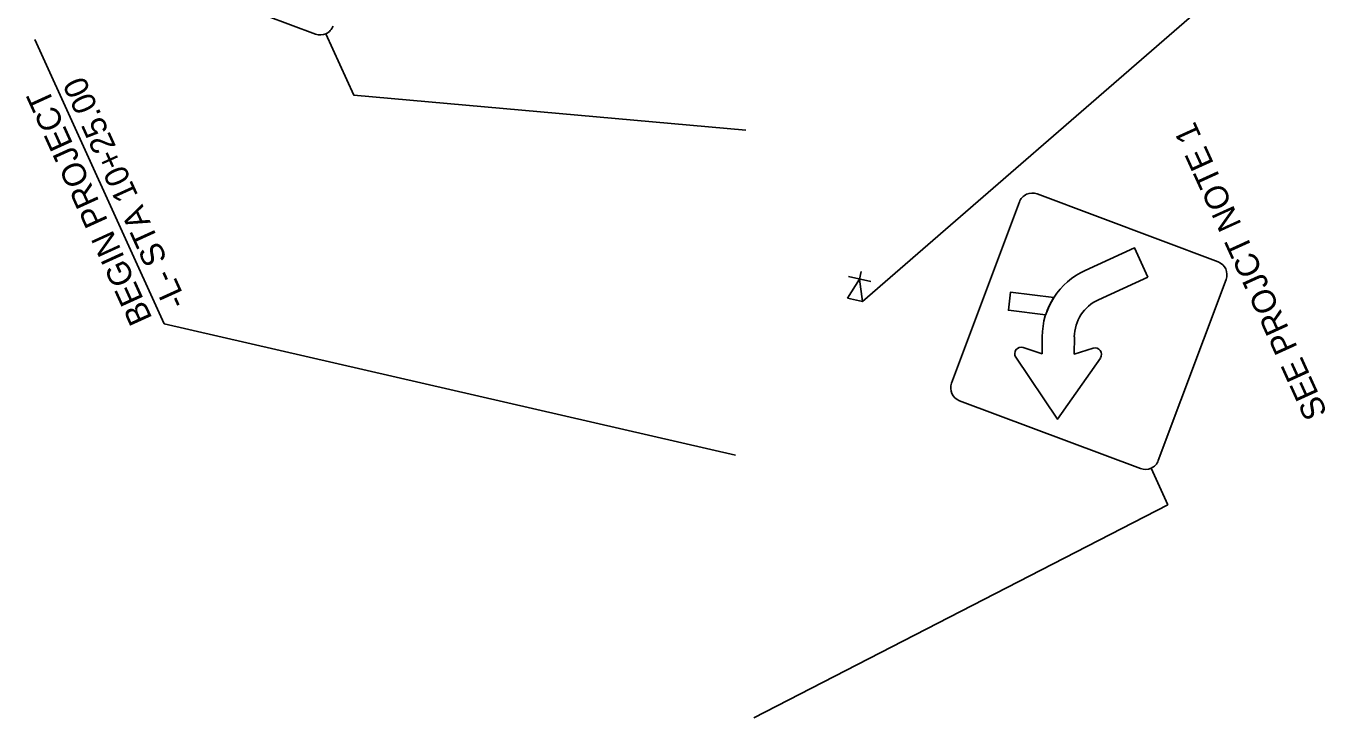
# Model space of a CAD drawing. Extents: x 2093420 to 2100301, y 676254 to 688367.
# Drawn here: x 2096431.2 to 2096816.5, y 683545.9 to 683750.8 of the extents above; entities that cross this region are included whole.
import ezdxf

# ---------------------------------------------------------------- set-up
doc = ezdxf.new("R2010")
doc.units = 0
for name, color, linetype in [('Default', 7, 'Continuous'), ('Exist Sign E Curve Left CELL', 7, 'Continuous'), ('Prop Horizontal Alignment Station Label', 7, 'Continuous')]:
    doc.layers.add(name, color=color, linetype=linetype)

msp = doc.modelspace()

# ---------------------------------------------------------------- linework, layer by layer
at = {"layer": 'Default'}
for p, q in [((2096678.06, 683675.89), (2096678.59, 683678.14)), ((2096674.52, 683670.25), (2096678.06, 683675.89)), ((2096681.4, 683675.11), (2096674.77, 683676.66)), ((2096678.06, 683675.89), (2096678.98, 683669.21)), ((2096678.98, 683669.21), (2096674.52, 683670.25)), ((2096764.44, 683619.87), (2096769.35, 683609.07))]:
    msp.add_line(p, q, dxfattribs=at)
for points in [[(2096775.78, 683769.09), (2096780.98, 683757.66), (2096678.98, 683669.21)], [(2096520.03, 683748.5), (2096528.29, 683730.35), (2096644.42, 683719.91)], [(2096769.35, 683609.07), (2096769.35, 683609.07), (2096646.79, 683545.94)]]:
    msp.add_lwpolyline(points, dxfattribs=at)
at = {"layer": 'Exist Sign E Curve Left CELL'}
for p, q in [((2096463.32, 683768.48), (2096516.91, 683748.4)), ((2096784.26, 683680.99), (2096730.67, 683701.07)), ((2096725.42, 683698.69), (2096705.34, 683645.1)), ((2096763.49, 683676.41), (2096748.87, 683669.77)), ((2096763.49, 683676.41), (2096748.87, 683669.77)), ((2096763.49, 683676.41), (2096748.87, 683669.77)), ((2096766.57, 683622.15), (2096786.65, 683675.74)), ((2096707.73, 683639.85), (2096761.32, 683619.76))]:
    msp.add_line(p, q, dxfattribs=at)
for points in [[(2096744.93, 683678.44), (2096759.54, 683685.08), (2096763.49, 683676.41)], [(2096744.93, 683678.44), (2096759.54, 683685.08), (2096763.49, 683676.41)], [(2096744.93, 683678.44), (2096759.54, 683685.08), (2096763.49, 683676.41)], [(2096735.65, 683670.43), (2096722.83, 683672.02), (2096722.16, 683666.62), (2096733.2, 683665.24)], [(2096726.53, 683655.59), (2096732.13, 683653.76), (2096732.18, 683658.81)], [(2096726.53, 683655.59), (2096732.13, 683653.76), (2096732.18, 683658.81)], [(2096726.53, 683655.59), (2096732.13, 683653.76), (2096732.18, 683658.81)], [(2096741.7, 683658.73), (2096741.66, 683653.68), (2096747.28, 683655.41)], [(2096741.7, 683658.73), (2096741.66, 683653.68), (2096747.28, 683655.41)], [(2096741.7, 683658.73), (2096741.66, 683653.68), (2096747.28, 683655.41)], [(2096749.41, 683652.5), (2096736.73, 683634.35), (2096724.36, 683652.71)], [(2096749.41, 683652.5), (2096736.73, 683634.35), (2096724.36, 683652.71)], [(2096749.41, 683652.5), (2096736.73, 683634.35), (2096724.36, 683652.71)]]:
    msp.add_lwpolyline(points, dxfattribs=at)
for centre, radius, start, end in [((2096518.34, 683752.22), 4.08, 249.458, 339.458), ((2096729.24, 683697.25), 4.08, 69.458, 159.458), ((2096782.83, 683677.17), 4.08, 339.458, 69.458), ((2096753.94, 683658.62), 21.77, 147.1671, 162.2946), ((2096709.16, 683643.66), 4.08, 159.458, 249.458), ((2096762.75, 683623.58), 4.08, 249.458, 339.458)]:
    msp.add_arc(centre, radius, start, end, dxfattribs=at)
for centre, major_axis, start_param, end_param in [((2096753.94, 683658.62), (-19.82, -9.01), 4.712389, 5.847944), ((2096753.94, 683658.62), (-19.82, -9.01), 4.712389, 5.847944), ((2096753.94, 683658.62), (-19.82, -9.01), 4.712389, 5.847944), ((2096753.94, 683658.62), (-11.15, -5.07), 4.712389, 5.847944), ((2096753.94, 683658.62), (-11.15, -5.07), 4.712389, 5.847944), ((2096753.94, 683658.62), (-11.15, -5.07), 4.712389, 5.847944), ((2096725.94, 683653.78), (-1.73, -0.79), 3.969953, 6.449197), ((2096725.94, 683653.78), (-1.73, -0.79), 3.969953, 6.449197), ((2096725.94, 683653.78), (-1.73, -0.79), 3.969953, 6.449197), ((2096747.85, 683653.6), (1.73, 0.79), 5.246691, 7.725935), ((2096747.85, 683653.6), (1.73, 0.79), 5.246691, 7.725935), ((2096747.85, 683653.6), (1.73, 0.79), 5.246691, 7.725935)]:
    msp.add_ellipse(centre, major_axis=major_axis, ratio=0.999989, start_param=start_param, end_param=end_param, dxfattribs=at)
at = {"layer": 'Prop Horizontal Alignment Station Label'}
for p, q in [((2096472.13, 683662.58), (2096433.81, 683746.84)), ((2096641.33, 683623.7), (2096472.13, 683662.58))]:
    msp.add_line(p, q, dxfattribs=at)

# ---------------------------------------------------------------- texts
at = {"layer": 'Default'}
msp.add_text('SEE PROJCT NOTE 1', height=7, rotation=114.4888, dxfattribs=at).set_placement((2096816.77, 683636.18))
at = {"layer": 'Prop Horizontal Alignment Station Label'}
for s, p in [('-L- STA 10+25.00', (2096478.96, 683668.9)), ('BEGIN PROJECT', (2096468.7, 683664.24))]:
    msp.add_text(s, height=7, rotation=114.458, dxfattribs=at).set_placement(p)

doc.saveas('drawing.dxf')
